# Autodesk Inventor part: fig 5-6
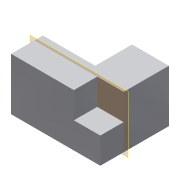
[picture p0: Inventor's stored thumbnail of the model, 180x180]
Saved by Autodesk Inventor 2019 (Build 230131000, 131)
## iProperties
Created: 2010-02
Part Number: fig 5-6
Document SubType Name: Modeling
Designer: CADSoft
Density: 1 g/cm^3
Material: Generic
Appearance: Default
Author: CADSoft
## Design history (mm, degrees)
sketch "Sketch1"
  geometry: L1 (0, 26.227)-(0, 12.145); L2 (0, 12.145)-(-20.026, 12.145); L3 (-20.026, 12.145)-(-20.026, 0); L4 (-20.026, 0)-(14.083, 0); L5 (14.083, 0)-(14.083, 26.227); L6 (14.083, 26.227)-(0, 26.227); 1 further point
  constraints: 12 end point
extrude "Extrusion1" new body sketch "Sketch1" distance "d0" = 20; taper "d1" = 0 deg
sketch "Sketch2"
  geometry: L1 (14.083, 0)-(3.983, 0); L2 (3.983, 0)-(3.983, 8.922); L3 (3.983, 8.922)-(14.083, 8.922); L4 (14.083, 8.922)-(14.083, 0); 1 further point
  constraints: 8 end point
extrude "Extrusion2" cut sketch "Sketch2" distance "d2" = 10; taper "d3" = 0 deg
workplane "Work Plane1"
body "Solid1"
